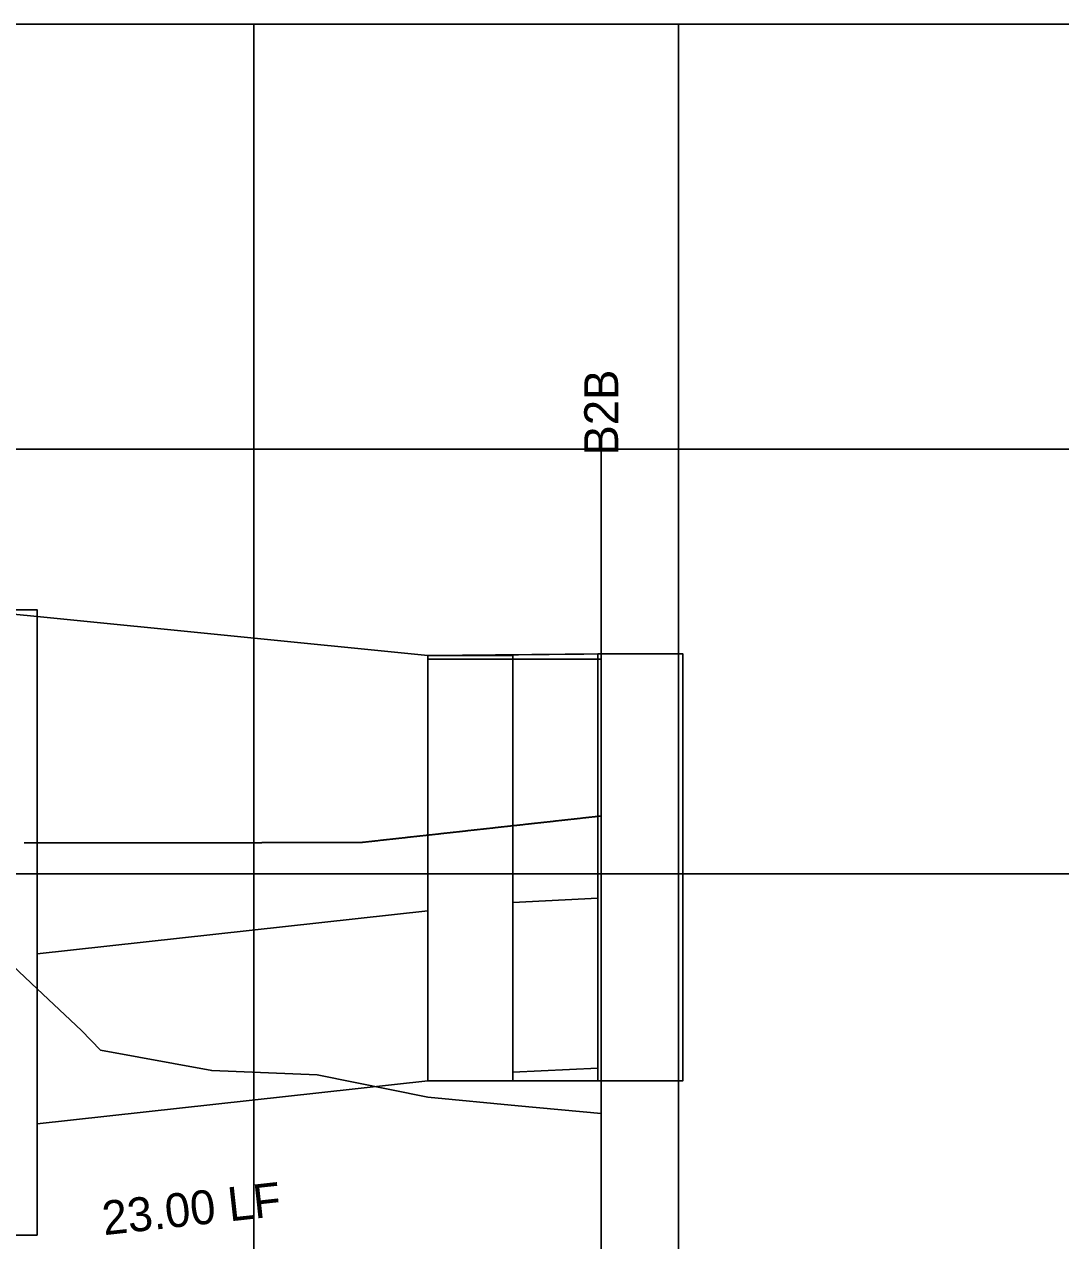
# Model space of a CAD drawing. Extents: x 2254979 to 2278074, y 13790855 to 13792793.
# Drawn here: x 2276910.9 to 2276971.9, y 13792721 to 13792792.6 of the extents above; entities that cross this region are included whole.
import ezdxf

# ---------------------------------------------------------------- set-up
doc = ezdxf.new("R2010")
doc.units = 0
for name, color, linetype in [('blank4', 7, 'Continuous'), ('BORD_grid_bottom_major_5int', 7, 'Continuous'), ('D_DRN_PROF_HGL', 7, 'Continuous'), ('D_PROF_1', 7, 'Continuous'), ('D_PROF_NOTES_1', 7, 'Continuous'), ('Drain_PipeInside', 7, 'Continuous'), ('E_Terrain', 7, 'Continuous'), ('Inlet', 7, 'Continuous'), ('z - Construction', 7, 'Continuous')]:
    doc.layers.add(name, color=color, linetype=linetype)

msp = doc.modelspace()

# ---------------------------------------------------------------- linework, layer by layer
at = {"layer": 'blank4'}
msp.add_lwpolyline([(2276874.404, 13792692.599), (2276874.404, 13792767.599), (2276944.852, 13792767.599), (2276944.852, 13792692.599)], close=True, dxfattribs=at)
at = {"layer": 'BORD_grid_bottom_major_5int'}
for p, q in [((2276749.404, 13792792.599), (2277074.404, 13792792.599)), ((2276924.404, 13792492.599), (2276924.404, 13792792.599)), ((2276949.404, 13792492.599), (2276949.404, 13792792.599)), ((2276749.404, 13792767.599), (2277074.404, 13792767.599)), ((2276749.404, 13792742.599), (2277074.404, 13792742.599))]:
    msp.add_line(p, q, dxfattribs=at)
at = {"layer": 'D_DRN_PROF_HGL'}
msp.add_lwpolyline([(2276910.893, 13792744.436), (2276910.939, 13792744.436), (2276910.984, 13792744.436), (2276911.03, 13792744.436), (2276911.076, 13792744.436), (2276911.121, 13792744.436), (2276911.167, 13792744.436), (2276911.212, 13792744.436), (2276911.258, 13792744.436), (2276911.304, 13792744.436), (2276911.349, 13792744.436), (2276911.395, 13792744.436), (2276911.44, 13792744.436), (2276911.486, 13792744.436), (2276911.532, 13792744.436), (2276911.577, 13792744.436), (2276911.623, 13792744.436), (2276911.669, 13792744.436), (2276911.714, 13792744.436), (2276911.76, 13792744.436), (2276911.805, 13792744.436), (2276911.851, 13792744.436), (2276911.897, 13792744.436), (2276911.942, 13792744.436), (2276911.988, 13792744.436), (2276912.033, 13792744.437), (2276912.079, 13792744.437), (2276912.125, 13792744.437), (2276912.17, 13792744.437), (2276912.216, 13792744.437), (2276912.262, 13792744.437), (2276912.307, 13792744.437), (2276912.353, 13792744.437), (2276912.398, 13792744.437), (2276912.444, 13792744.437), (2276912.49, 13792744.437), (2276912.535, 13792744.437), (2276912.581, 13792744.437), (2276912.627, 13792744.437), (2276912.672, 13792744.437), (2276912.718, 13792744.437), (2276912.763, 13792744.437), (2276912.809, 13792744.437), (2276912.855, 13792744.437), (2276912.9, 13792744.437), (2276912.946, 13792744.437), (2276912.991, 13792744.437), (2276913.037, 13792744.437), (2276913.083, 13792744.437), (2276913.128, 13792744.437), (2276913.174, 13792744.437), (2276913.22, 13792744.437), (2276913.265, 13792744.437), (2276913.311, 13792744.437), (2276913.356, 13792744.437), (2276913.402, 13792744.437), (2276913.448, 13792744.437), (2276913.493, 13792744.437), (2276913.539, 13792744.437), (2276913.584, 13792744.437), (2276913.63, 13792744.437), (2276913.676, 13792744.437), (2276913.721, 13792744.437), (2276913.767, 13792744.437), (2276913.813, 13792744.437), (2276913.858, 13792744.437), (2276913.904, 13792744.437), (2276913.949, 13792744.437), (2276913.995, 13792744.437), (2276914.041, 13792744.437), (2276914.086, 13792744.437), (2276914.132, 13792744.437), (2276914.177, 13792744.437), (2276914.223, 13792744.437), (2276914.269, 13792744.437), (2276914.314, 13792744.437), (2276914.36, 13792744.437), (2276914.406, 13792744.437), (2276914.451, 13792744.437), (2276914.497, 13792744.437), (2276914.542, 13792744.437), (2276914.588, 13792744.437), (2276914.634, 13792744.438), (2276914.679, 13792744.438), (2276914.725, 13792744.438), (2276914.77, 13792744.438), (2276914.816, 13792744.438), (2276914.862, 13792744.438), (2276914.907, 13792744.438), (2276914.953, 13792744.438), (2276914.999, 13792744.438), (2276915.044, 13792744.438), (2276915.09, 13792744.438), (2276915.135, 13792744.438), (2276915.181, 13792744.438), (2276915.227, 13792744.438), (2276915.272, 13792744.438), (2276915.318, 13792744.438), (2276915.363, 13792744.438), (2276915.409, 13792744.438), (2276915.455, 13792744.438), (2276915.5, 13792744.438), (2276915.546, 13792744.438), (2276915.592, 13792744.438), (2276915.637, 13792744.438), (2276915.683, 13792744.438), (2276915.728, 13792744.438), (2276915.774, 13792744.438), (2276915.82, 13792744.438), (2276915.865, 13792744.438), (2276915.911, 13792744.438), (2276915.956, 13792744.438), (2276916.002, 13792744.438), (2276916.048, 13792744.438), (2276916.093, 13792744.438), (2276916.139, 13792744.438), (2276916.185, 13792744.438), (2276916.23, 13792744.438), (2276916.276, 13792744.438), (2276916.321, 13792744.438), (2276916.367, 13792744.438), (2276916.413, 13792744.438), (2276916.458, 13792744.438), (2276916.504, 13792744.438), (2276916.549, 13792744.438), (2276916.595, 13792744.438), (2276916.641, 13792744.438), (2276916.686, 13792744.438), (2276916.732, 13792744.438), (2276916.778, 13792744.438), (2276916.823, 13792744.438), (2276916.869, 13792744.438), (2276916.914, 13792744.438), (2276916.96, 13792744.438), (2276917.006, 13792744.438), (2276917.051, 13792744.438), (2276917.097, 13792744.438), (2276917.142, 13792744.438), (2276917.188, 13792744.439), (2276917.234, 13792744.439), (2276917.279, 13792744.439), (2276917.325, 13792744.439), (2276917.371, 13792744.439), (2276917.416, 13792744.439), (2276917.462, 13792744.439), (2276917.507, 13792744.439), (2276917.553, 13792744.439), (2276917.599, 13792744.439), (2276917.644, 13792744.439), (2276917.69, 13792744.439), (2276917.735, 13792744.439), (2276917.781, 13792744.439), (2276917.827, 13792744.439), (2276917.872, 13792744.439), (2276917.918, 13792744.439), (2276917.964, 13792744.439), (2276918.009, 13792744.439), (2276918.055, 13792744.439), (2276918.1, 13792744.439), (2276918.146, 13792744.439), (2276918.192, 13792744.439), (2276918.237, 13792744.439), (2276918.283, 13792744.439), (2276918.328, 13792744.439), (2276918.374, 13792744.439), (2276918.42, 13792744.439), (2276918.465, 13792744.439), (2276918.511, 13792744.439), (2276918.557, 13792744.439), (2276918.602, 13792744.439), (2276918.648, 13792744.439), (2276918.693, 13792744.439), (2276918.739, 13792744.439), (2276918.785, 13792744.439), (2276918.83, 13792744.439), (2276918.876, 13792744.439), (2276918.921, 13792744.439), (2276918.967, 13792744.439), (2276919.013, 13792744.439), (2276919.058, 13792744.439), (2276919.104, 13792744.439), (2276919.15, 13792744.439), (2276919.195, 13792744.439), (2276919.241, 13792744.439), (2276919.286, 13792744.439), (2276919.332, 13792744.439), (2276919.378, 13792744.439), (2276919.423, 13792744.439), (2276919.469, 13792744.439), (2276919.514, 13792744.439), (2276919.56, 13792744.439), (2276919.606, 13792744.439), (2276919.651, 13792744.439), (2276919.697, 13792744.439), (2276919.743, 13792744.44), (2276919.788, 13792744.44), (2276919.834, 13792744.44), (2276919.879, 13792744.44), (2276919.925, 13792744.44), (2276919.971, 13792744.44), (2276920.016, 13792744.44), (2276920.062, 13792744.44), (2276920.107, 13792744.44), (2276920.153, 13792744.44), (2276920.199, 13792744.44), (2276920.244, 13792744.44), (2276920.29, 13792744.44), (2276920.336, 13792744.44), (2276920.381, 13792744.44), (2276920.427, 13792744.44), (2276920.472, 13792744.44), (2276920.518, 13792744.44), (2276920.564, 13792744.44), (2276920.609, 13792744.44), (2276920.655, 13792744.44), (2276920.7, 13792744.44), (2276920.746, 13792744.44), (2276920.792, 13792744.44), (2276920.837, 13792744.44), (2276920.883, 13792744.44), (2276920.929, 13792744.44), (2276920.974, 13792744.44), (2276921.02, 13792744.44), (2276921.065, 13792744.44), (2276921.111, 13792744.44), (2276921.157, 13792744.44), (2276921.202, 13792744.44), (2276921.248, 13792744.44), (2276921.293, 13792744.44), (2276921.339, 13792744.44), (2276921.385, 13792744.44), (2276921.43, 13792744.44), (2276921.476, 13792744.44), (2276921.522, 13792744.44), (2276921.567, 13792744.44), (2276921.613, 13792744.44), (2276921.658, 13792744.44), (2276921.704, 13792744.44), (2276921.75, 13792744.44), (2276921.795, 13792744.44), (2276921.841, 13792744.44), (2276921.886, 13792744.44), (2276921.932, 13792744.44), (2276921.978, 13792744.44), (2276922.023, 13792744.44), (2276922.069, 13792744.44), (2276922.115, 13792744.44), (2276922.16, 13792744.44), (2276922.206, 13792744.44), (2276922.251, 13792744.44), (2276922.297, 13792744.44), (2276922.343, 13792744.441), (2276922.388, 13792744.441), (2276922.434, 13792744.441), (2276922.479, 13792744.441), (2276922.525, 13792744.441), (2276922.571, 13792744.441), (2276922.616, 13792744.441), (2276922.662, 13792744.441), (2276922.708, 13792744.441), (2276922.753, 13792744.441), (2276922.799, 13792744.441), (2276922.844, 13792744.441), (2276922.89, 13792744.441), (2276922.936, 13792744.441), (2276922.981, 13792744.441), (2276923.027, 13792744.441), (2276923.072, 13792744.441), (2276923.118, 13792744.441), (2276923.164, 13792744.441), (2276923.209, 13792744.441), (2276923.255, 13792744.441), (2276923.301, 13792744.441), (2276923.346, 13792744.441), (2276923.392, 13792744.441), (2276923.437, 13792744.441), (2276923.483, 13792744.441), (2276923.529, 13792744.441), (2276923.574, 13792744.441), (2276923.62, 13792744.441), (2276923.666, 13792744.441), (2276923.711, 13792744.441), (2276923.757, 13792744.441), (2276923.802, 13792744.441), (2276923.848, 13792744.441), (2276923.894, 13792744.441), (2276923.939, 13792744.441), (2276923.985, 13792744.441), (2276924.03, 13792744.441), (2276924.076, 13792744.441), (2276924.122, 13792744.441), (2276924.167, 13792744.441), (2276924.213, 13792744.441), (2276924.259, 13792744.441), (2276924.304, 13792744.441), (2276924.35, 13792744.441), (2276924.395, 13792744.441), (2276924.441, 13792744.441), (2276924.487, 13792744.441), (2276924.532, 13792744.441), (2276924.578, 13792744.441), (2276924.623, 13792744.441), (2276924.669, 13792744.441), (2276924.715, 13792744.441), (2276924.76, 13792744.441), (2276924.806, 13792744.441), (2276924.852, 13792744.441), (2276924.897, 13792744.442), (2276924.943, 13792744.442), (2276924.988, 13792744.442), (2276925.034, 13792744.442), (2276925.08, 13792744.442), (2276925.125, 13792744.442), (2276925.171, 13792744.442), (2276925.216, 13792744.442), (2276925.262, 13792744.442), (2276925.308, 13792744.442), (2276925.353, 13792744.442), (2276925.399, 13792744.442), (2276925.445, 13792744.442), (2276925.49, 13792744.442), (2276925.536, 13792744.442), (2276925.581, 13792744.442), (2276925.627, 13792744.442), (2276925.673, 13792744.442), (2276925.718, 13792744.442), (2276925.764, 13792744.442), (2276925.809, 13792744.442), (2276925.855, 13792744.442), (2276925.901, 13792744.442), (2276925.946, 13792744.442), (2276925.992, 13792744.442), (2276926.038, 13792744.442), (2276926.083, 13792744.442), (2276926.129, 13792744.442), (2276926.174, 13792744.442), (2276926.22, 13792744.442), (2276926.266, 13792744.442), (2276926.311, 13792744.442), (2276926.357, 13792744.442), (2276926.402, 13792744.442), (2276926.448, 13792744.442), (2276926.494, 13792744.442), (2276926.539, 13792744.442), (2276926.585, 13792744.442), (2276926.631, 13792744.442), (2276926.676, 13792744.442), (2276926.722, 13792744.442), (2276926.767, 13792744.442), (2276926.813, 13792744.442), (2276926.859, 13792744.442), (2276926.904, 13792744.442), (2276926.95, 13792744.442), (2276926.995, 13792744.442), (2276927.041, 13792744.442), (2276927.087, 13792744.442), (2276927.132, 13792744.442), (2276927.178, 13792744.442), (2276927.224, 13792744.442), (2276927.269, 13792744.442), (2276927.315, 13792744.442), (2276927.36, 13792744.442), (2276927.406, 13792744.442), (2276927.452, 13792744.442), (2276927.497, 13792744.443), (2276927.543, 13792744.443), (2276927.588, 13792744.443), (2276927.634, 13792744.443), (2276927.68, 13792744.443), (2276927.725, 13792744.443), (2276927.771, 13792744.443), (2276927.817, 13792744.443), (2276927.862, 13792744.443), (2276927.908, 13792744.443), (2276927.953, 13792744.443), (2276927.999, 13792744.443), (2276928.045, 13792744.443), (2276928.09, 13792744.443), (2276928.136, 13792744.443), (2276928.181, 13792744.443), (2276928.227, 13792744.443), (2276928.273, 13792744.443), (2276928.318, 13792744.443), (2276928.364, 13792744.443), (2276928.41, 13792744.443), (2276928.455, 13792744.443), (2276928.501, 13792744.443), (2276928.546, 13792744.443), (2276928.592, 13792744.443), (2276928.638, 13792744.443), (2276928.683, 13792744.443), (2276928.729, 13792744.443), (2276928.774, 13792744.443), (2276928.82, 13792744.443), (2276928.866, 13792744.443), (2276928.911, 13792744.443), (2276928.957, 13792744.443), (2276929.003, 13792744.443), (2276929.048, 13792744.443), (2276929.094, 13792744.443), (2276929.139, 13792744.443), (2276929.185, 13792744.443), (2276929.231, 13792744.443), (2276929.276, 13792744.443), (2276929.322, 13792744.443), (2276929.367, 13792744.443), (2276929.413, 13792744.443), (2276929.459, 13792744.443), (2276929.504, 13792744.443), (2276929.55, 13792744.443), (2276929.596, 13792744.443), (2276929.641, 13792744.443), (2276929.687, 13792744.443), (2276929.732, 13792744.443), (2276929.778, 13792744.443), (2276929.824, 13792744.443), (2276929.869, 13792744.443), (2276929.915, 13792744.443), (2276929.96, 13792744.443), (2276930.006, 13792744.443), (2276930.052, 13792744.444), (2276930.097, 13792744.444), (2276930.143, 13792744.444), (2276930.189, 13792744.444), (2276930.234, 13792744.444), (2276930.28, 13792744.444), (2276930.325, 13792744.444), (2276930.371, 13792744.444), (2276930.417, 13792744.444), (2276930.462, 13792744.444), (2276930.508, 13792744.444), (2276930.553, 13792744.444), (2276930.599, 13792744.444), (2276930.645, 13792744.444), (2276930.69, 13792744.448), (2276930.736, 13792744.453), (2276930.782, 13792744.458), (2276930.827, 13792744.463), (2276930.873, 13792744.468), (2276930.918, 13792744.473), (2276930.964, 13792744.478), (2276931.01, 13792744.483), (2276931.055, 13792744.488), (2276931.101, 13792744.493), (2276931.146, 13792744.498), (2276931.192, 13792744.503), (2276931.238, 13792744.508), (2276931.283, 13792744.513), (2276931.329, 13792744.518), (2276931.375, 13792744.523), (2276931.42, 13792744.528), (2276931.466, 13792744.533), (2276931.511, 13792744.538), (2276931.557, 13792744.543), (2276931.603, 13792744.548), (2276931.648, 13792744.553), (2276931.694, 13792744.558), (2276931.739, 13792744.564), (2276931.785, 13792744.569), (2276931.831, 13792744.574), (2276931.876, 13792744.579), (2276931.922, 13792744.584), (2276931.968, 13792744.589), (2276932.013, 13792744.594), (2276932.059, 13792744.599), (2276932.104, 13792744.604), (2276932.15, 13792744.609), (2276932.196, 13792744.614), (2276932.241, 13792744.619), (2276932.287, 13792744.624), (2276932.332, 13792744.629), (2276932.378, 13792744.634), (2276932.424, 13792744.639), (2276932.469, 13792744.644), (2276932.515, 13792744.649), (2276932.561, 13792744.654), (2276932.606, 13792744.659), (2276932.652, 13792744.664), (2276932.697, 13792744.669), (2276932.743, 13792744.674), (2276932.789, 13792744.679), (2276932.834, 13792744.684), (2276932.88, 13792744.689), (2276932.925, 13792744.694), (2276932.971, 13792744.699), (2276933.017, 13792744.705), (2276933.062, 13792744.71), (2276933.108, 13792744.715), (2276933.154, 13792744.72), (2276933.199, 13792744.725), (2276933.245, 13792744.73), (2276933.29, 13792744.735), (2276933.336, 13792744.74), (2276933.382, 13792744.745), (2276933.427, 13792744.75), (2276933.473, 13792744.755), (2276933.518, 13792744.76), (2276933.564, 13792744.765), (2276933.61, 13792744.77), (2276933.655, 13792744.775), (2276933.701, 13792744.78), (2276933.747, 13792744.785), (2276933.792, 13792744.79), (2276933.838, 13792744.795), (2276933.883, 13792744.8), (2276933.929, 13792744.805), (2276933.975, 13792744.81), (2276934.02, 13792744.815), (2276934.066, 13792744.82), (2276934.111, 13792744.825), (2276934.157, 13792744.83), (2276934.203, 13792744.835), (2276934.248, 13792744.84), (2276934.294, 13792744.846), (2276934.34, 13792744.851), (2276934.385, 13792744.856), (2276934.431, 13792744.861), (2276934.476, 13792744.866), (2276934.522, 13792744.871), (2276934.568, 13792744.876), (2276934.613, 13792744.881), (2276934.659, 13792744.886), (2276934.704, 13792744.891), (2276934.75, 13792744.896), (2276934.796, 13792744.901), (2276934.841, 13792744.906), (2276934.887, 13792744.911), (2276934.933, 13792744.916), (2276934.978, 13792744.921), (2276935.024, 13792744.926), (2276935.069, 13792744.931), (2276935.115, 13792744.936), (2276935.161, 13792744.941), (2276935.206, 13792744.946), (2276935.252, 13792744.951), (2276935.298, 13792744.956), (2276935.343, 13792744.961), (2276935.389, 13792744.966), (2276935.434, 13792744.971), (2276935.48, 13792744.976), (2276935.526, 13792744.981), (2276935.571, 13792744.987), (2276935.617, 13792744.992), (2276935.662, 13792744.997), (2276935.708, 13792745.002), (2276935.754, 13792745.007), (2276935.799, 13792745.012), (2276935.845, 13792745.017), (2276935.891, 13792745.022), (2276935.936, 13792745.027), (2276935.982, 13792745.032), (2276936.027, 13792745.037), (2276936.073, 13792745.042), (2276936.119, 13792745.047), (2276936.164, 13792745.052), (2276936.21, 13792745.057), (2276936.255, 13792745.062), (2276936.301, 13792745.067), (2276936.347, 13792745.072), (2276936.392, 13792745.077), (2276936.438, 13792745.082), (2276936.484, 13792745.087), (2276936.529, 13792745.092), (2276936.575, 13792745.097), (2276936.62, 13792745.102), (2276936.666, 13792745.107), (2276936.712, 13792745.112), (2276936.757, 13792745.117), (2276936.803, 13792745.122), (2276936.848, 13792745.127), (2276936.894, 13792745.133), (2276936.94, 13792745.138), (2276936.985, 13792745.143), (2276937.031, 13792745.148), (2276937.077, 13792745.153), (2276937.122, 13792745.158), (2276937.168, 13792745.163), (2276937.213, 13792745.168), (2276937.259, 13792745.173), (2276937.305, 13792745.178), (2276937.35, 13792745.183), (2276937.396, 13792745.188), (2276937.441, 13792745.193), (2276937.487, 13792745.198), (2276937.533, 13792745.203), (2276937.578, 13792745.208), (2276937.624, 13792745.213), (2276937.67, 13792745.218), (2276937.715, 13792745.223), (2276937.761, 13792745.228), (2276937.806, 13792745.233), (2276937.852, 13792745.238), (2276937.898, 13792745.243), (2276937.943, 13792745.248), (2276937.989, 13792745.253), (2276938.034, 13792745.258), (2276938.08, 13792745.263), (2276938.126, 13792745.268), (2276938.171, 13792745.274), (2276938.217, 13792745.279), (2276938.263, 13792745.284), (2276938.308, 13792745.289), (2276938.354, 13792745.294), (2276938.399, 13792745.299), (2276938.445, 13792745.304), (2276938.491, 13792745.309), (2276938.536, 13792745.314), (2276938.582, 13792745.319), (2276938.627, 13792745.324), (2276938.673, 13792745.329), (2276938.719, 13792745.334), (2276938.764, 13792745.339), (2276938.81, 13792745.344), (2276938.856, 13792745.349), (2276938.901, 13792745.354), (2276938.947, 13792745.359), (2276938.992, 13792745.364), (2276939.038, 13792745.369), (2276939.084, 13792745.374), (2276939.129, 13792745.379), (2276939.175, 13792745.384), (2276939.22, 13792745.389), (2276939.266, 13792745.394), (2276939.312, 13792745.399), (2276939.357, 13792745.404), (2276939.403, 13792745.409), (2276939.449, 13792745.415), (2276939.494, 13792745.42), (2276939.54, 13792745.425), (2276939.585, 13792745.43), (2276939.631, 13792745.435), (2276939.677, 13792745.44), (2276939.722, 13792745.445), (2276939.768, 13792745.45), (2276939.813, 13792745.455), (2276939.859, 13792745.46), (2276939.905, 13792745.465), (2276939.95, 13792745.47), (2276939.996, 13792745.475), (2276940.042, 13792745.48), (2276940.087, 13792745.485), (2276940.133, 13792745.49), (2276940.178, 13792745.495), (2276940.224, 13792745.5), (2276940.27, 13792745.505), (2276940.315, 13792745.51), (2276940.361, 13792745.515), (2276940.406, 13792745.52), (2276940.452, 13792745.525), (2276940.498, 13792745.53), (2276940.543, 13792745.535), (2276940.589, 13792745.54), (2276940.635, 13792745.545), (2276940.68, 13792745.55), (2276940.726, 13792745.556), (2276940.771, 13792745.561), (2276940.817, 13792745.566), (2276940.863, 13792745.571), (2276940.908, 13792745.576), (2276940.954, 13792745.581), (2276940.999, 13792745.586), (2276941.045, 13792745.591), (2276941.091, 13792745.596), (2276941.136, 13792745.601), (2276941.182, 13792745.606), (2276941.228, 13792745.611), (2276941.273, 13792745.616), (2276941.319, 13792745.621), (2276941.364, 13792745.626), (2276941.41, 13792745.631), (2276941.456, 13792745.636), (2276941.501, 13792745.641), (2276941.547, 13792745.646), (2276941.592, 13792745.651), (2276941.638, 13792745.656), (2276941.684, 13792745.661), (2276941.729, 13792745.666), (2276941.775, 13792745.671), (2276941.821, 13792745.676), (2276941.866, 13792745.681), (2276941.912, 13792745.686), (2276941.957, 13792745.691), (2276942.003, 13792745.696), (2276942.049, 13792745.702), (2276942.094, 13792745.707), (2276942.14, 13792745.712), (2276942.185, 13792745.717), (2276942.231, 13792745.722), (2276942.277, 13792745.727), (2276942.322, 13792745.732), (2276942.368, 13792745.737), (2276942.414, 13792745.742), (2276942.459, 13792745.747), (2276942.505, 13792745.752), (2276942.55, 13792745.757), (2276942.596, 13792745.762), (2276942.642, 13792745.767), (2276942.687, 13792745.772), (2276942.733, 13792745.777), (2276942.778, 13792745.782), (2276942.824, 13792745.787), (2276942.87, 13792745.792), (2276942.915, 13792745.797), (2276942.961, 13792745.802), (2276943.007, 13792745.807), (2276943.052, 13792745.812), (2276943.098, 13792745.817), (2276943.143, 13792745.822), (2276943.189, 13792745.827), (2276943.235, 13792745.832), (2276943.28, 13792745.837), (2276943.326, 13792745.843), (2276943.371, 13792745.848), (2276943.417, 13792745.853), (2276943.463, 13792745.858), (2276943.508, 13792745.863), (2276943.554, 13792745.868), (2276943.6, 13792745.873), (2276943.645, 13792745.878), (2276943.691, 13792745.883), (2276943.736, 13792745.888), (2276943.782, 13792745.893), (2276943.828, 13792745.898), (2276943.873, 13792745.903), (2276943.919, 13792745.908), (2276943.964, 13792745.913), (2276944.01, 13792745.918), (2276944.056, 13792745.923), (2276944.101, 13792745.928), (2276944.147, 13792745.933), (2276944.193, 13792745.938), (2276944.238, 13792745.943), (2276944.284, 13792745.948), (2276944.329, 13792745.953), (2276944.375, 13792745.958), (2276944.421, 13792745.963), (2276944.466, 13792745.968), (2276944.512, 13792745.973), (2276944.557, 13792745.978), (2276944.603, 13792745.984), (2276944.649, 13792745.989), (2276944.694, 13792745.994), (2276944.74, 13792745.999), (2276944.786, 13792746.004), (2276944.831, 13792746.009), (2276944.852, 13792746.008), (2276944.852, 13792747.612)], dxfattribs=at)
at = {"layer": 'D_PROF_1'}
msp.add_lwpolyline([(2276907.654, 13792758.146), (2276911.654, 13792757.746), (2276911.654, 13792757.746), (2276934.654, 13792755.446), (2276934.654, 13792755.446), (2276934.785, 13792755.447), (2276935.674, 13792755.456), (2276935.798, 13792755.457), (2276936.694, 13792755.466), (2276936.812, 13792755.467), (2276937.714, 13792755.476), (2276938.628, 13792755.485), (2276938.734, 13792755.486), (2276938.838, 13792755.487), (2276939.753, 13792755.496), (2276939.885, 13792755.497), (2276939.899, 13792755.498), (2276939.982, 13792755.498), (2276940.773, 13792755.506), (2276940.865, 13792755.507), (2276941.793, 13792755.517), (2276942.733, 13792755.528), (2276942.813, 13792755.528), (2276942.881, 13792755.529), (2276943.703, 13792755.539), (2276943.712, 13792755.539), (2276943.836, 13792755.54), (2276944.817, 13792755.551), (2276944.852, 13792755.552)], dxfattribs=at)
at = {"layer": 'Drain_PipeInside'}
for p, q in [((2276939.654, 13792740.929), (2276944.654, 13792741.179)), ((2276911.654, 13792737.899), (2276934.654, 13792740.429)), ((2276939.654, 13792730.929), (2276944.654, 13792731.179)), ((2276911.654, 13792727.899), (2276934.654, 13792730.429))]:
    msp.add_line(p, q, dxfattribs=at)
at = {"layer": 'E_Terrain'}
msp.add_lwpolyline([(2276907.654, 13792739.6), (2276911.654, 13792735.846), (2276911.654, 13792735.846), (2276914.276, 13792733.386), (2276915.381, 13792732.235), (2276921.931, 13792731.033), (2276928.128, 13792730.772), (2276934.654, 13792729.461), (2276934.654, 13792729.461), (2276939.962, 13792728.958), (2276944.852, 13792728.505)], dxfattribs=at)
at = {"layer": 'Inlet'}
for points in [[(2276903.654, 13792758.146), (2276911.654, 13792758.146), (2276911.654, 13792721.349), (2276903.654, 13792721.349)], [(2276934.654, 13792730.429), (2276939.654, 13792730.429), (2276939.654, 13792755.446), (2276934.654, 13792755.446)], [(2276944.654, 13792730.429), (2276949.654, 13792730.429), (2276949.654, 13792755.549), (2276944.654, 13792755.549)], [(2276934.654, 13792755.246), (2276944.852, 13792755.246), (2276944.852, 13792730.429), (2276934.654, 13792730.429)]]:
    msp.add_lwpolyline(points, close=True, dxfattribs=at)
at = {"layer": 'z - Construction'}
msp.add_line((2276874.404, 13792742.599), (2276944.852, 13792742.599), dxfattribs=at)

# ---------------------------------------------------------------- texts
at = {"layer": 'D_PROF_NOTES_1'}
for s, rotation, p in [('B2B', 90, (2276945.852, 13792767.223)), ('23.00 LF', 6.2773, (2276915.594, 13792721.338))]:
    msp.add_text(s, height=2, rotation=rotation, dxfattribs=at).set_placement(p)

doc.saveas('drawing.dxf')
